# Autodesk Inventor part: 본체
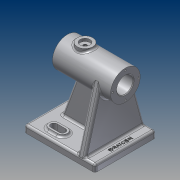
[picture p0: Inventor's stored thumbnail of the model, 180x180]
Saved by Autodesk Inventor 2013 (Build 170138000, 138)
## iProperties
Created: 2019-10
Part Number: 본체
Material: 알루미늄 6061
Document SubType Name: Modeling
Designer: user
Density: 2.71 g/cm^3
Mass: 588.38 g
Surface Area: 540.191 cm^2
Volume: 217.115 cm^3
Author: user
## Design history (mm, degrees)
sketch "스케치1"
  geometry: L1 (-25, 0)-(57, 0); L2 (-25, 0)-(-25, 21); L3 (-25, 21)-(57, 21); L4 (-25, 0)-(-25, 14.5); L5 (-25, 14.5)-(37, 14.5); L6 (37, 14.5)-(37, 11.5); L7 (57, 21)-(57, 0); L8 (37, 11.5)-(57, 11.5); 1 further point
  constraints: 16 end point, 5 perpendicular, 3 point on line, 1 horizontal
  dimensions: "d0" = 82 distance of L1.start L1.end; "d1" = 25 distance of point (0, 0) L1.start; "d3" = 82 distance of L2.end L3.end; "d5" = 42 diameter of L3 L1; "d10" = 29 diameter of L5 L1; "d11" = 62 distance between parallel lines of L2 L6; "d12" = 23 diameter of L6.end L1
revolve "회전1" sketch "스케치1" stored, may be unused: angle "d13" = 90 deg
node "작업 평면1"
sketch "스케치2"
  geometry: L1 (-57, 21)-(-57, -21) reference; L2 (-57, -43)-(43, -43); L3 (43, -43)-(43, 43); L4 (43, 43)-(-57, 43); L5 (-57, 43)-(-57, -43); L6 (-57, -43)-(43, 43); L7 (43, -43)-(-57, 43); 3 further points
  constraints: 12 end point, 4 midpoint, 2 parallel, 1 horizontal, 1 perpendicular
  dimensions: "d15" = 100 distance of L4.end L3.end; "d16" = 86 distance of L3.end L2.end
extrude "돌출1" join sketch "스케치2" distance "d17" = 10; taper "d18" = 0 deg
fillet "모깎기1" dims "d19" = 3
sketch "스케치4"
  geometry: L1 (-43, 40)-(-43, -40) reference; L2 (57, -40)-(57, 40) reference; L3 (54, 43)-(-40, 43) reference; L4 (57, 0)-(42, 0); L5 (-43, 0)-(-28, 0); L6 (7, -5)-(42, -5); L7 (42, -5)-(42, 5); L8 (42, 5)-(7, 5); L9 (7, 5)-(7, -5); 1 further point
  constraints: 12 end point, 3 midpoint, 3 parallel, 1 collinear, 1 horizontal, 1 perpendicular
  dimensions: "d26" = 15 distance of L4.end L4.start; "d27" = 15 distance of L5.start L5.end; "d28" = 35 distance of L8.end L7.end; "d29" = 10 distance of L7.end L6.end
extrude "돌출3" join sketch "스케치4" stored distance "d30" = 10; taper "d31" = 0 deg
sketch "스케치5"
  geometry: L1 (37, -11.5)-(57, -11.5) reference; L2 (57, -11.5)-(57, -21) reference; L3 (57, -21)-(42, -21) reference; L4 (42, -21)-(42, -76) reference; L5 (42, -76)-(57, -76) reference; L6 (57, -76)-(57, -86) reference; L7 (57, -86)-(-43, -86) reference; L8 (-43, -86)-(-43, -76) reference; L9 (-43, -76)-(7, -76) reference; L10 (7, -76)-(7, -21) reference; L11 (7, -21)-(-25, -21) reference; L12 (-25, -21)-(-25, -14.5) reference; L13 (-25, -14.5)-(37, -14.5) reference; L14 (37, -14.5)-(37, -11.5) reference; L15 (-25, 21)-(57, 21) reference; L16 (57, 21)-(57, 11.5) reference; L17 (57, 11.5)-(37, 11.5) reference; L18 (37, 11.5)-(37, 14.5) reference; L19 (37, 14.5)-(-25, 14.5) reference; L20 (-25, 14.5)-(-25, 21) reference; L21 (-28, -76)-(-7.982, -21); 1 further point
  constraints: 2 end point, 2 point on line
  dimensions: "d32" = 15 distance of L21.start L8.end; "d33" = 70 deg angle of L9 L21
feature "리브1" sketch "스케치5" dims "d34" = 1, "d35" = 10, "d36" = 0, "d37" = 0, "d38" = 1, "d39" = 1
node "작업 평면2"
fillet "모깎기3" dims "d41" = 3
sketch "스케치6"
  geometry: L1 (83, 7)-(83, 0) reference; L2 (83, 0)-(-3, 0) reference; L3 (-3, 0)-(-3, 7) reference; L4 (0, 10)-(35, 10) reference; L5 (35, 10)-(35, 65.604) reference; L6 (45, 65.604)-(45, 10) reference; L7 (45, 10)-(80, 10) reference; L8 (-3, 7)-(19.721, 91.456); L9 (83, 7)-(60.279, 91.456); C1 r 14.5 at (40, 86) reference; C2 r 11.5 at (40, 86) reference; A1 r 3 centre (80, 7) between (83, 7) and (80, 10) reference; A2 r 3 centre (0, 7) between (0, 10) and (-3, 7) reference; A3 r 21 centre (40, 86) between (45, 65.604) and (35, 65.604) reference; 1 further point
  constraints: 4 end point, 2 point on circle, 2 tangent
extrude "돌출4" join sketch "스케치6" stored distance "d42" = 10; taper "d43" = 0 deg
fillet "모깎기4" dims "d44" = 3
fillet "모깎기5" dims "d45" = 3
sketch "스케치7"
  geometry: L1 (0, 0)-(0, 18); C1 r 21 at (0, 0) reference; 1 further point
  constraints: 2 end point, 1 coincident, 1 vertical
  dimensions: "d46" = 18 distance of L1.start L1.end
hole "구멍1" sketch "스케치7" at (0, 18) diameter "d47" = 2.459; stored, may be unused: countersink angle "d51" = 90 deg, drill point angle "d53" = 118 deg; dims "d48" = 8, "d49" = 4, "d50" = 2, "d52" = 10
sketch "스케치8"
  geometry: L1 (0, 0)-(0, 18); C1 r 14.5 at (0, 0) reference; 1 further point
  constraints: 2 end point, 1 coincident, 1 vertical
  dimensions: "d57" = 18 distance of L1.start L1.end
hole "구멍2" sketch "스케치8" at (0, 18) diameter "d58" = 2.459; stored, may be unused: countersink angle "d62" = 90 deg, drill point angle "d64" = 118 deg; dims "d59" = 8, "d60" = 4, "d61" = 2, "d63" = 10
chamfer "모따기1" distance "d68" = 1; stored, may be unused: second distance "d69" = 2, angle "d70" = 45 deg
sketch "스케치9"
  geometry: L1 (-30.101, 2)-(-30.101, -2) reference; L2 (-43, 40)-(-43, -40) reference; L3 (-43, 0)-(-30.101, 0); L4 (-43, 0)-(-43, 27); L5 (-43, 27)-(-17, 27); L6 (-17, 34)-(-5, 34); L7 (-5, 34)-(-5, 20); L8 (-5, 20)-(-17, 20); L9 (-17, 20)-(-17, 34); 3 further points
  constraints: 14 end point, 4 midpoint, 2 parallel, 2 perpendicular, 2 vertical alignment, 1 coincident, 1 horizontal, 1 point on line, 4 other
  dimensions: "d74" = 27 distance of L3.start L4.end; "d76" = 26 distance of L5.end L4.end; "d77" = 12 distance of L7.end L8.end; "d78" = 14 distance of L6.end L7.end
extrude "돌출5" join sketch "스케치9" distance "d79" = 3; taper "d80" = 0 deg
sketch "스케치10"
  geometry: L1 (-17, 31.5)-(-5, 31.5); L2 (-17, 22.5)-(-5, 22.5); A1 r 7 centre (-5, 27) between (-5, 20) and (-5, 34) reference; A2 r 7 centre (-17, 27) between (-17, 34) and (-17, 20) reference; A3 r 4.5 centre (-17, 27) between (-17, 31.5) and (-17, 22.5); A4 r 4.5 centre (-5, 27) between (-5, 31.5) and (-5, 22.5); 1 further point
  constraints: 4 end point, 4 point on circle, 4 tangent, 2 centre point, 2 coincident
  dimensions: "d81" = 9 diameter of A3; "d82" = 9 diameter of A4
extrude "돌출6" cut sketch "스케치10" stored distance "d83" = 0; taper "d84" = 0 deg
fillet "모깎기6" dims "d85" = 3
node "작업 평면3"
sketch "스케치11"
  geometry: C1 r 11 at (0, 0); 1 further point
  constraints: 1 centre point, 1 coincident
  dimensions: "d87" = 22 diameter of C1
extrude "돌출7" join sketch "스케치11" stored distance "d88" = 3; taper "d89" = 0 deg
sketch "스케치12"
  geometry: C1 r 11 at (0, 0) reference; C2 r 7 at (0, 0)
  constraints: 1 centre point, 1 coincident
  dimensions: "d90" = 14 diameter of C2
extrude "돌출8" cut sketch "스케치12" distance "d91" = 4; taper "d92" = 0 deg
sketch "스케치13"
  geometry: C1 r 7 at (0, 0) reference; 1 further point
  constraints: 1 coincident
hole "구멍3" sketch "스케치13" at (0, 0) diameter "d93" = 4.917; stored, may be unused: countersink angle "d97" = 90 deg, drill point angle "d99" = 118 deg; dims "d94" = 8, "d95" = 4, "d96" = 2, "d98" = 10
fillet "모깎기7" dims "d100" = 3
sketch "스케치14"
  geometry: L1 (57, -40)-(57, 40) reference; 3 further points
  constraints: 1 horizontal alignment, 1 midpoint, 1 other
  dimensions: "d101" = 7 distance from line of L1 point (50, 0)
feature "엠보싱1" sketch "스케치14" dims "d102" = 0.5, "d103" = 0
node "솔리드1"
pattern_circular "원형 패턴1" dims angle "d55" = 360 deg
pattern_circular "원형 패턴2" dims angle "d66" = 360 deg
mirror "대칭1"
node "절단 모서리 투영1"
node "절단 모서리 투영2"
other parameters: "d14" = -86, "d86" = 24
